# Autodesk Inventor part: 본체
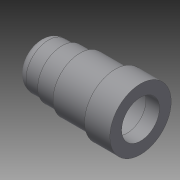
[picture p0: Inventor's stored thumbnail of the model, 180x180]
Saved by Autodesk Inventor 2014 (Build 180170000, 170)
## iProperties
Created: 2016-06
Part Number: 본체
Material: 일반
Document SubType Name: Modeling
Designer: SEC
Density: 1 g/cm^3
Appearance: 기본값
Author: SEC
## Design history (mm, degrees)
sketch "스케치1"
  geometry: L1 (-56, 0)-(56, 0); L2 (-56, 0)-(-56, 15); L3 (-46, 25)-(-31, 25); L4 (-31, 25)-(-31, 27); L5 (-31, 27)-(-11, 27); L6 (-11, 27)-(-11, 30); L7 (-11, 30)-(28, 30); L8 (28, 30)-(28, 34); L9 (28, 34)-(56, 34); L10 (56, 34)-(56, 21); L11 (56, 21)-(41, 21); L12 (41, 21)-(41, 24); L13 (41, 24)-(-13, 24); L14 (-13, 24)-(-13, 21); L15 (-13, 21)-(-25, 21); L16 (-25, 21)-(-25, 17.5); L17 (-25, 17.5)-(-43, 17.5); L18 (-43, 17.5)-(-43, 16); L19 (-43, 16)-(-47, 16); L20 (-47, 16)-(-47, 10.5); L21 (-47, 10.5)-(-50, 10.5); L22 (-50, 10.5)-(-50, 0); A1 r 10 centre (-46, 15) between (-46, 25) and (-56, 15); 3 further points
  constraints: 44 end point, 17 parallel, 4 perpendicular, 3 point on line, 2 point on circle, 2 tangent, 1 centre point, 1 coincident, 1 horizontal, 1 midpoint, 1 vertical alignment
  dimensions: "d0" = 112 distance of L1.start L1.end; "d1" = 42 diameter of L11 L1; "d2" = 48 diameter of L13 L1; "d3" = 42 diameter of L15 L1; "d4" = 35 diameter of L17 L1; "d5" = 32 diameter of L19 L1; "d6" = 21 diameter of L21 L1; "d7" = 15 distance of L10.end L11.end; "d8" = 54 distance of L12.end L13.end; "d9" = 12 distance of L14.end L15.end; "d10" = 18 distance of L16.end L17.end; "d11" = 3 distance of L20.end L21.end; "d12" = 4 distance of L18.end L19.end; "d13" = 25 distance of point (-56, 25) L3.end; "d14" = 45 horizontal distance of L5.end point (-56, 25); "d15" = 84 horizontal distance of L7.end point (-56, 25); "d16" = 68 diameter of L9 L1; "d17" = 60 diameter of L7 L1; "d18" = 54 diameter of L5 L1; "d19" = 50 diameter of L3 L1; "d20" = 10 radius of A1
revolve "회전1" sketch "스케치1" stored, may be unused: angle "d21" = 90 deg
node "솔리드1"
